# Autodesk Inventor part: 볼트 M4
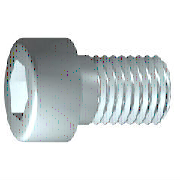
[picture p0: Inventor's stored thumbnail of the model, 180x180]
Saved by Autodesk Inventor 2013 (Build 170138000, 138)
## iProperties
IsCustomPart: 1
Created: 2012-02
Part Number: 볼트 M4
Material: 강철, 연강
Description: 6각머리 태핑 나사
Document SubType Name: Modeling
Standard: KS B 1003
Designer: mduedu
Standards Organization: KS
Language: ko-KR
Size Designation: M 4 x 10
Categories: <MemberInstance><Categories><Category DisplayName="조임쇠" InternalName="e4da775c-781d-43d5-af7c-5136215cf5a6" Mnemonic="FSTN"><Category DisplayName="볼트" InternalN
Density: 1 g/cm^3
Author: mduedu
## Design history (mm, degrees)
sketch "스케치1"
  geometry: L1 (-1, 0)-(10, 0); L2 (10, 0)-(10, 2); L3 (10, 2)-(1.75, 2); L4 (1.75, 2)-(1.32, 2); L5 (1.32, 2)-(0, 2); L6 (0, 2)-(0, 3.5); L7 (0, 3.5)-(-4, 3.5); L8 (-4, 3.5)-(-4, 1.732); L9 (-4, 1.732)-(-2, 1.732); L10 (-2, 1.732)-(-1, 0); L11 (-6.8, 0)-(12.8, 0) reference; L12 (0, -0.7)-(0, 4.2) reference; L13 (1.75, 2)-(0, 2)
  constraints: 22 end point, 6 parallel, 2 collinear, 2 perpendicular, 1 horizontal, 1 point on line
  dimensions: "d1" = 8.25 distance from line of L3.end L2 (= GEL); "d2" = 0.42952 distance of L4.end L3.end (computed from GAL); "d3" = 4 distance between parallel lines of L8 L6 (= KOH); "d4" = 2 distance of L8.end L9.end (= INTI); "d5" = 60 deg angle of L10 L1; "d6" = 4 diameter of L3 L1 (= GD); "d7" = 4 diameter of L5 L1 (= BDM); "d8" = 3.4641 diameter of L9 L1 (= 1.1547 x SW); "d9" = 7 diameter of L7 L1 (= KOD); "d26" = 10 distance between parallel lines of L12 L2 (= NLG)
revolve "본체" sketch "스케치1" stored, may be unused: angle "d10" = 90 deg
sketch "스케치2"
  geometry: L1 (0, -4.9)-(0, 4.9) reference; L2 (-4.9, 0)-(4.9, 0) reference; L3 (1.732, 0)-(0.866, -1.5); L4 (0.866, -1.5)-(-0.866, -1.5); L5 (-0.866, -1.5)-(-1.732, 0); L6 (-1.732, 0)-(-0.866, 1.5); L7 (-0.866, 1.5)-(0.866, 1.5); L8 (0.866, 1.5)-(1.732, 0); 2 further points
  constraints: 12 end point, 1 coincident, 1 horizontal alignment, 1 point on line, 12 other
extrude "슬롯" join sketch "스케치2" stored distance "d11" = 10; taper "d12" = 0 deg
workplane "Work Plane1"
fillet "Fillet2" dims "d30" = 0.1 (= R)
body "Solid1"
fillet "모깎기1" dims "d17" = 0.4 (= RR)
feature "스레드" dims "d13" = 8.25 (= GEL), "d14" = 0
chamfer "모따기1" distance "d15" = 0.42941 (= -0.5 x SPD + 0.5 x GD); stored, may be unused: second distance "d16" = 0.42941 (= GUL), angle "d27" = 45 deg
other parameters: "GD" = 4 (= NND) [user parameter; used in 2 equation terms], "NLG" = 10 [user parameter; used in 1 equation term], "GEL" = 8.25 [user parameter; used in 2 equation terms], "KOD" = 7 [user parameter; used in 1 equation term], "KOH" = 4 [user parameter; used in 1 equation term], "INTI" = 2 [user parameter; used in 1 equation term], "GAL" = 0.42941 (= 0.61345 x PTC) [user parameter; used in 1 equation term], "GUL" = 0.42941 (= 0.61345 x PTC) [user parameter; used in 1 equation term], "BDM" = 4 (= NND) [user parameter; used in 1 equation term], "SW" = 3 [user parameter; used in 2 equation terms], "RR" = 0.4 [user parameter; used in 1 equation term], "SPD" = 3.14117 (= NND - 1.2269 x PTC) [user parameter; used in 1 equation term], "d19" = 0, "d28" = 0, "d29" = 0, "R" = 0.1 [user parameter; used in 1 equation term], "PHH" = 0.2 [user parameter], "GD1" = 3.14117 (= THREADDIA - 1.2269 x PTC) [user parameter], "THREADDIA" = 4 [user parameter; used in 1 equation term], "FAWI" = 45 deg [user parameter], "TPU" = 14.28571 (computed from PTC) [user parameter], "PTC" = 0.7 [user parameter; used in 5 equation terms], "NND" = 4 [user parameter; used in 3 equation terms], "TOA" = 30 deg [user parameter], "E0" = 3.465 (= 1.155 x SW) [user parameter]
